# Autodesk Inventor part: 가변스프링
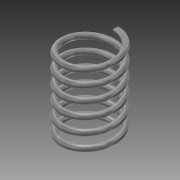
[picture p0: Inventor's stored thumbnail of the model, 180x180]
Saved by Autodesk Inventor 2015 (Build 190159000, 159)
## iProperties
Created: 2015-10
Part Number: 가변스프링
Material: Steel, Carbon
Document SubType Name: Modeling
Designer: youjin14
Density: 7.85 g/cm^3
Appearance: Semi-Polished
Mass: 128.854 g
Surface Area: 132.999 cm^2
Volume: 16.4145 cm^3
Author: youjin14
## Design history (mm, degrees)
sketch "Sketch1"
  geometry: L1 (0, 0)-(22.5, 0); L2 (22.5, 0)-(22.5, 73.25); L3 (22.5, 73.25)-(0, 73.25); L4 (0, 73.25)-(0, 0); C1 r 2.5 at (22.5, 0)
  constraints: 8 end point, 2 parallel, 1 centre point, 1 coincident, 1 horizontal, 1 perpendicular
  dimensions: "d0" = 73.25 distance between parallel lines of L1 L3 (derived); "d1" = 5 diameter of C1; "d2" = 45 diameter of L2 L4
coil "Coil1" sketch "Sketch1" pitch "d3" = 10; turns "d5" = 6; dims "d4" = 73.25 (= d0), "d6" = 0, angle "d7" = 90 deg, angle "d8" = 90 deg, "d9" = 0, "d10" = 0
sketch "Sketch2"
  geometry: L1 (0, 25)-(0, 20) reference; 1 further point
  constraints: 1 vertical alignment
extrude "Extrusion1" cut sketch "Sketch2" stored distance "d11" = 10; taper "d12" = 0 deg
workplane "Work Plane1"
sketch "Sketch3"
  geometry: L1 (0, 25)-(0, 20) reference; 1 further point
  constraints: 1 vertical alignment
extrude "Extrusion2" cut sketch "Sketch3" stored distance "d13" = 10; taper "d14" = 0 deg
body "Solid1"
node "Project Cut Edges1"
node "Project Cut Edges2"
